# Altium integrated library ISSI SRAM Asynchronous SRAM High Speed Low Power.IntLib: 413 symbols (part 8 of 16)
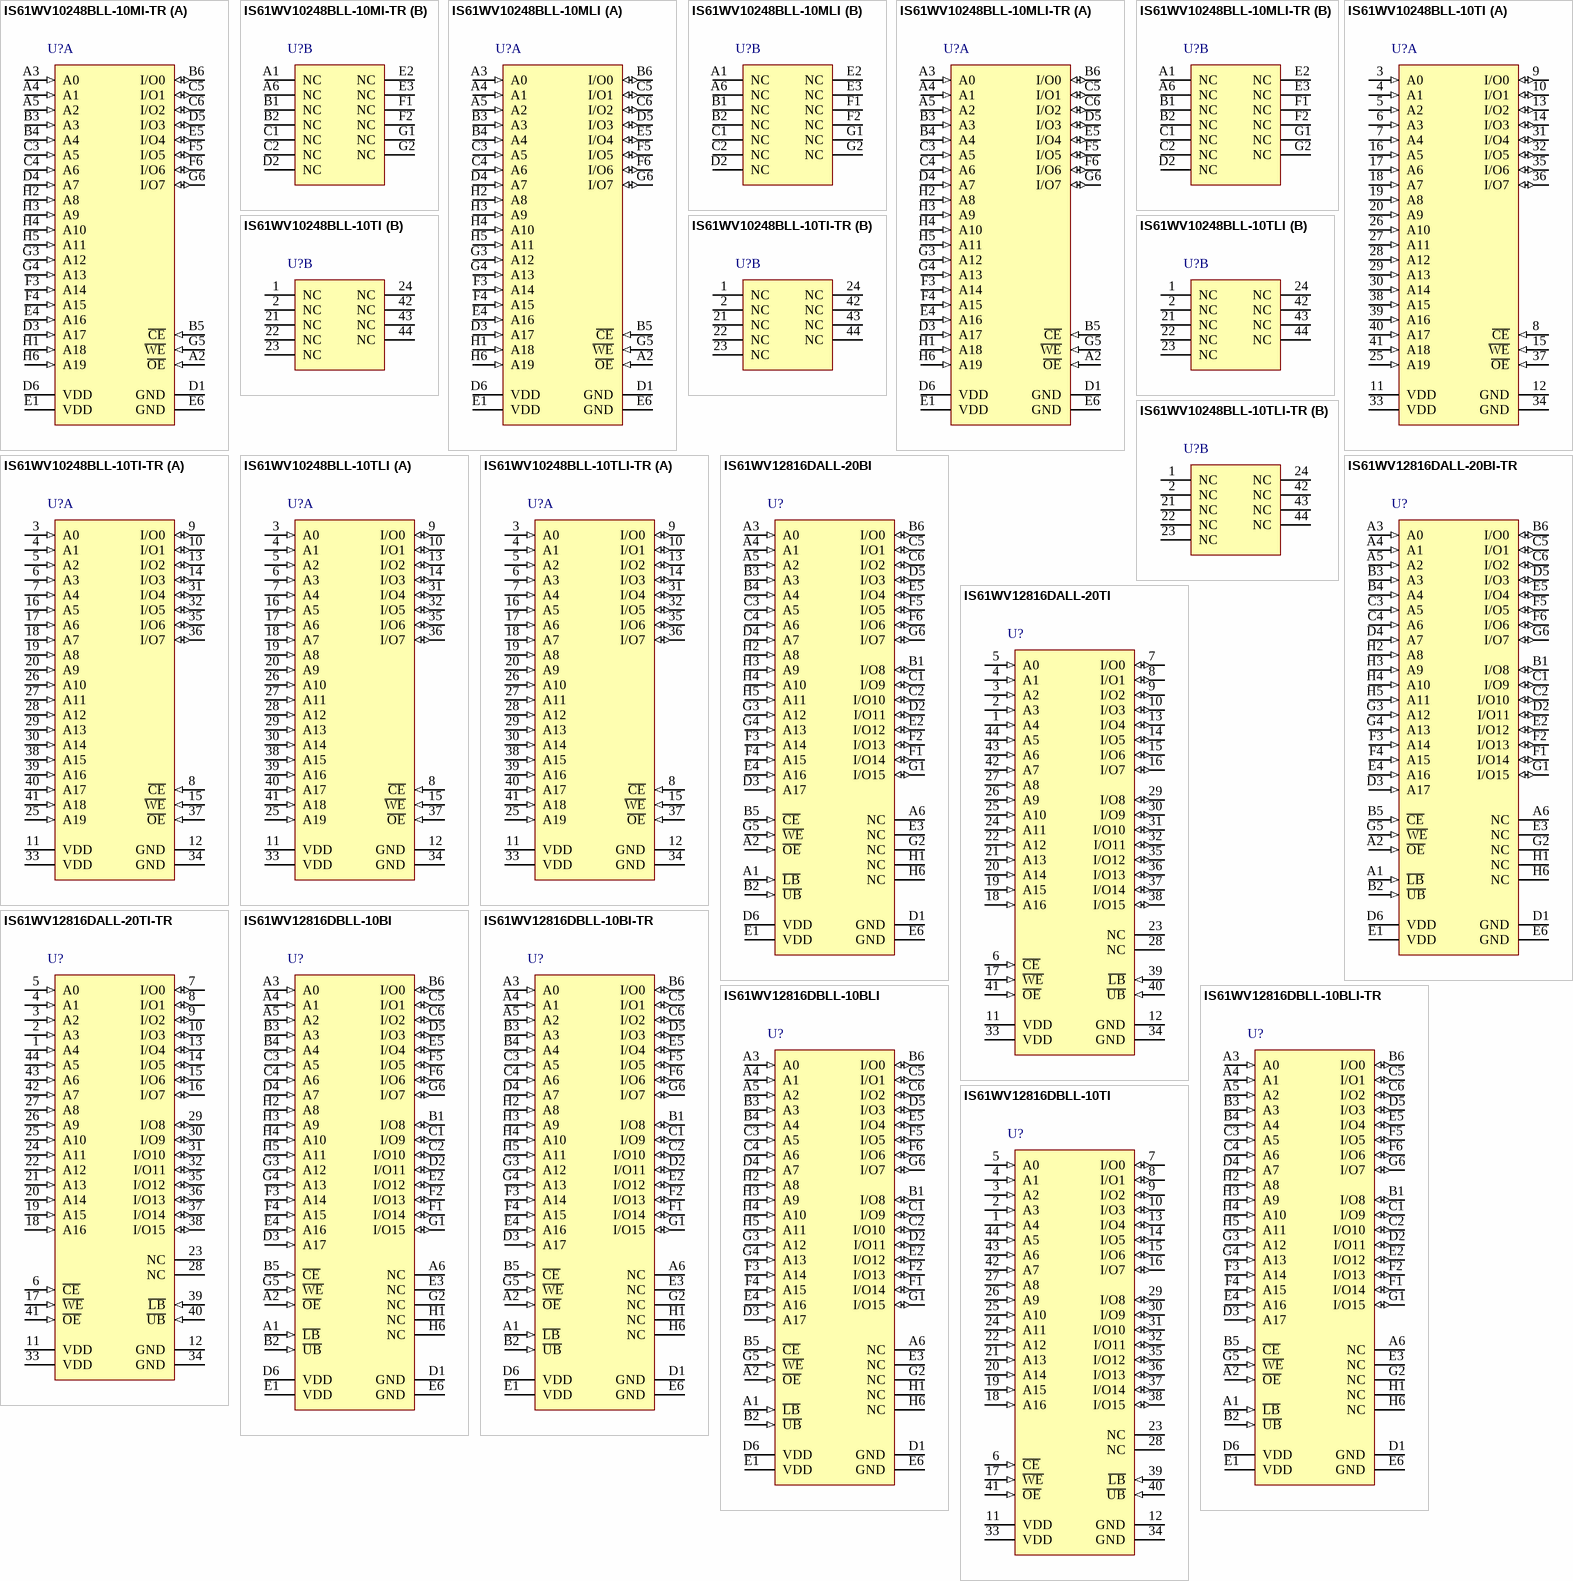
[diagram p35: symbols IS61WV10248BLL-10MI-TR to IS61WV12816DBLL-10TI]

## IS61WV12816DBLL-10BLI
designator U?
2 M High Speed Asynchronous CMOS SRAM, 128 K x 16, -40 to 85 degC, 48-Pin BGA (TF-BGA-48), Pb-Free; Manufacturer: Integrated Silicon Solution Inc (ISSI); PartNumber: IS61WV12816DBLL-10BLI; Packing: Tray / Tube; Speed (ns): 10
footprint ISSI-TF-BGA-48-6000X8000DE (BGA, 48-Balls, Body 8x6mm, Pitch 0.75mm)
pins: A1 ~{LB} (in) "Lower-byte Control (I/O0-I/O7)", A2 ~{OE} (in) "Output Enable Input", A3 A0 (in) "Address Input", A4 A1 (in) "Address Input", A5 A2 (in) "Address Input", A6 NC "No Connection", B1 I/O8 (io) "Data Input/Output", B2 ~{UB} (in) "Upper-byte Control (I/O8-I/O15)", B3 A3 (in) "Address Input", B4 A4 (in) "Address Input", B5 ~{CE} (in) "Chip Enable Input", B6 I/O0 (io) "Data Input/Output", C1 I/O9 (io) "Data Input/Output", C2 I/O10 (io) "Data Input/Output", C3 A5 (in) "Address Input", C4 A6 (in) "Address Input", C5 I/O1 (io) "Data Input/Output", C6 I/O2 (io) "Data Input/Output", D1 GND (power) "Ground", D2 I/O11 (io) "Data Input/Output", D3 A17 (in) "Address Input", D4 A7 (in) "Address Input", D5 I/O3 (io) "Data Input/Output", D6 VDD (power) "Power", E1 VDD (power) "Power", E2 I/O12 (io) "Data Input/Output", E3 NC "No Connection", E4 A16 (in) "Address Input", E5 I/O4 (io) "Data Input/Output", E6 GND (power) "Ground", F1 I/O14 (io) "Data Input/Output", F2 I/O13 (io) "Data Input/Output", F3 A14 (in) "Address Input", F4 A15 (in) "Address Input", F5 I/O5 (io) "Data Input/Output", F6 I/O6 (io) "Data Input/Output", G1 I/O15 (io) "Data Input/Output", G2 NC "No Connection", G3 A12 (in) "Address Input", G4 A13 (in) "Address Input", G5 ~{WE} (in) "Write Enable Input", G6 I/O7 (io) "Data Input/Output", H1 NC "No Connection", H2 A8 (in) "Address Input", H3 A9 (in) "Address Input", H4 A10 (in) "Address Input", H5 A11 (in) "Address Input", H6 NC "No Connection"

## IS61WV12816DBLL-10BLI-TR
designator U?
2 M High Speed Asynchronous CMOS SRAM, 128 K x 16, -40 to 85 degC, 48-Pin BGA (TF-BGA-48), Pb-Free; Manufacturer: Integrated Silicon Solution Inc (ISSI); PartNumber: IS61WV12816DBLL-10BLI-TR; Packing: Tape & Reel; Speed (ns): 10
footprint ISSI-TF-BGA-48-6000X8000DE (BGA, 48-Balls, Body 8x6mm, Pitch 0.75mm)
pins: A1 ~{LB} (in) "Lower-byte Control (I/O0-I/O7)", A2 ~{OE} (in) "Output Enable Input", A3 A0 (in) "Address Input", A4 A1 (in) "Address Input", A5 A2 (in) "Address Input", A6 NC "No Connection", B1 I/O8 (io) "Data Input/Output", B2 ~{UB} (in) "Upper-byte Control (I/O8-I/O15)", B3 A3 (in) "Address Input", B4 A4 (in) "Address Input", B5 ~{CE} (in) "Chip Enable Input", B6 I/O0 (io) "Data Input/Output", C1 I/O9 (io) "Data Input/Output", C2 I/O10 (io) "Data Input/Output", C3 A5 (in) "Address Input", C4 A6 (in) "Address Input", C5 I/O1 (io) "Data Input/Output", C6 I/O2 (io) "Data Input/Output", D1 GND (power) "Ground", D2 I/O11 (io) "Data Input/Output", D3 A17 (in) "Address Input", D4 A7 (in) "Address Input", D5 I/O3 (io) "Data Input/Output", D6 VDD (power) "Power", E1 VDD (power) "Power", E2 I/O12 (io) "Data Input/Output", E3 NC "No Connection", E4 A16 (in) "Address Input", E5 I/O4 (io) "Data Input/Output", E6 GND (power) "Ground", F1 I/O14 (io) "Data Input/Output", F2 I/O13 (io) "Data Input/Output", F3 A14 (in) "Address Input", F4 A15 (in) "Address Input", F5 I/O5 (io) "Data Input/Output", F6 I/O6 (io) "Data Input/Output", G1 I/O15 (io) "Data Input/Output", G2 NC "No Connection", G3 A12 (in) "Address Input", G4 A13 (in) "Address Input", G5 ~{WE} (in) "Write Enable Input", G6 I/O7 (io) "Data Input/Output", H1 NC "No Connection", H2 A8 (in) "Address Input", H3 A9 (in) "Address Input", H4 A10 (in) "Address Input", H5 A11 (in) "Address Input", H6 NC "No Connection"

## IS61WV12816DBLL-10TI
designator U?
2 M High Speed Asynchronous CMOS SRAM, 128 K x 16, -40 to 85 degC, 44-Pin SOP (TSOP-2-44); Manufacturer: Integrated Silicon Solution Inc (ISSI); PartNumber: IS61WV12816DBLL-10TI; Packing: Tray / Tube; Speed (ns): 10
footprint ISSI-TSOP-2-44_N (SOP, 44-Leads, Body 18.5x10.3mm, Pitch 0.8mm, IPC Medium Density)
pins: 1 A4 (in) "Address Input", 2 A3 (in) "Address Input", 3 A2 (in) "Address Input", 4 A1 (in) "Address Input", 5 A0 (in) "Address Input", 6 ~{CE} (in) "Chip Enable Input", 7 I/O0 (io) "Data Input/Output", 8 I/O1 (io) "Data Input/Output", 9 I/O2 (io) "Data Input/Output", 10 I/O3 (io) "Data Input/Output", 11 VDD (power) "Power", 12 GND (power) "Ground", 13 I/O4 (io) "Data Input/Output", 14 I/O5 (io) "Data Input/Output", 15 I/O6 (io) "Data Input/Output", 16 I/O7 (io) "Data Input/Output", 17 ~{WE} (in) "Write Enable Input", 18 A16 (in) "Address Input", 19 A15 (in) "Address Input", 20 A14 (in) "Address Input", 21 A13 (in) "Address Input", 22 A12 (in) "Address Input", 23 NC "No Connection", 24 A11 (in) "Address Input", 25 A10 (in) "Address Input", 26 A9 (in) "Address Input", 27 A8 (in) "Address Input", 28 NC "No Connection", 29 I/O8 (io) "Data Input/Output", 30 I/O9 (io) "Data Input/Output", 31 I/O10 (io) "Data Input/Output", 32 I/O11 (io) "Data Input/Output", 33 VDD (power) "Power", 34 GND (power) "Ground", 35 I/O12 (io) "Data Input/Output", 36 I/O13 (io) "Data Input/Output", 37 I/O14 (io) "Data Input/Output", 38 I/O15 (io) "Data Input/Output", 39 ~{LB} (in) "Lower-byte Control (I/O0-I/O7)", 40 ~{UB} (in) "Upper-byte Control (I/O8-I/O15)", 41 ~{OE} (in) "Output Enable Input", 42 A7 (in) "Address Input", 43 A6 (in) "Address Input", 44 A5 (in) "Address Input"

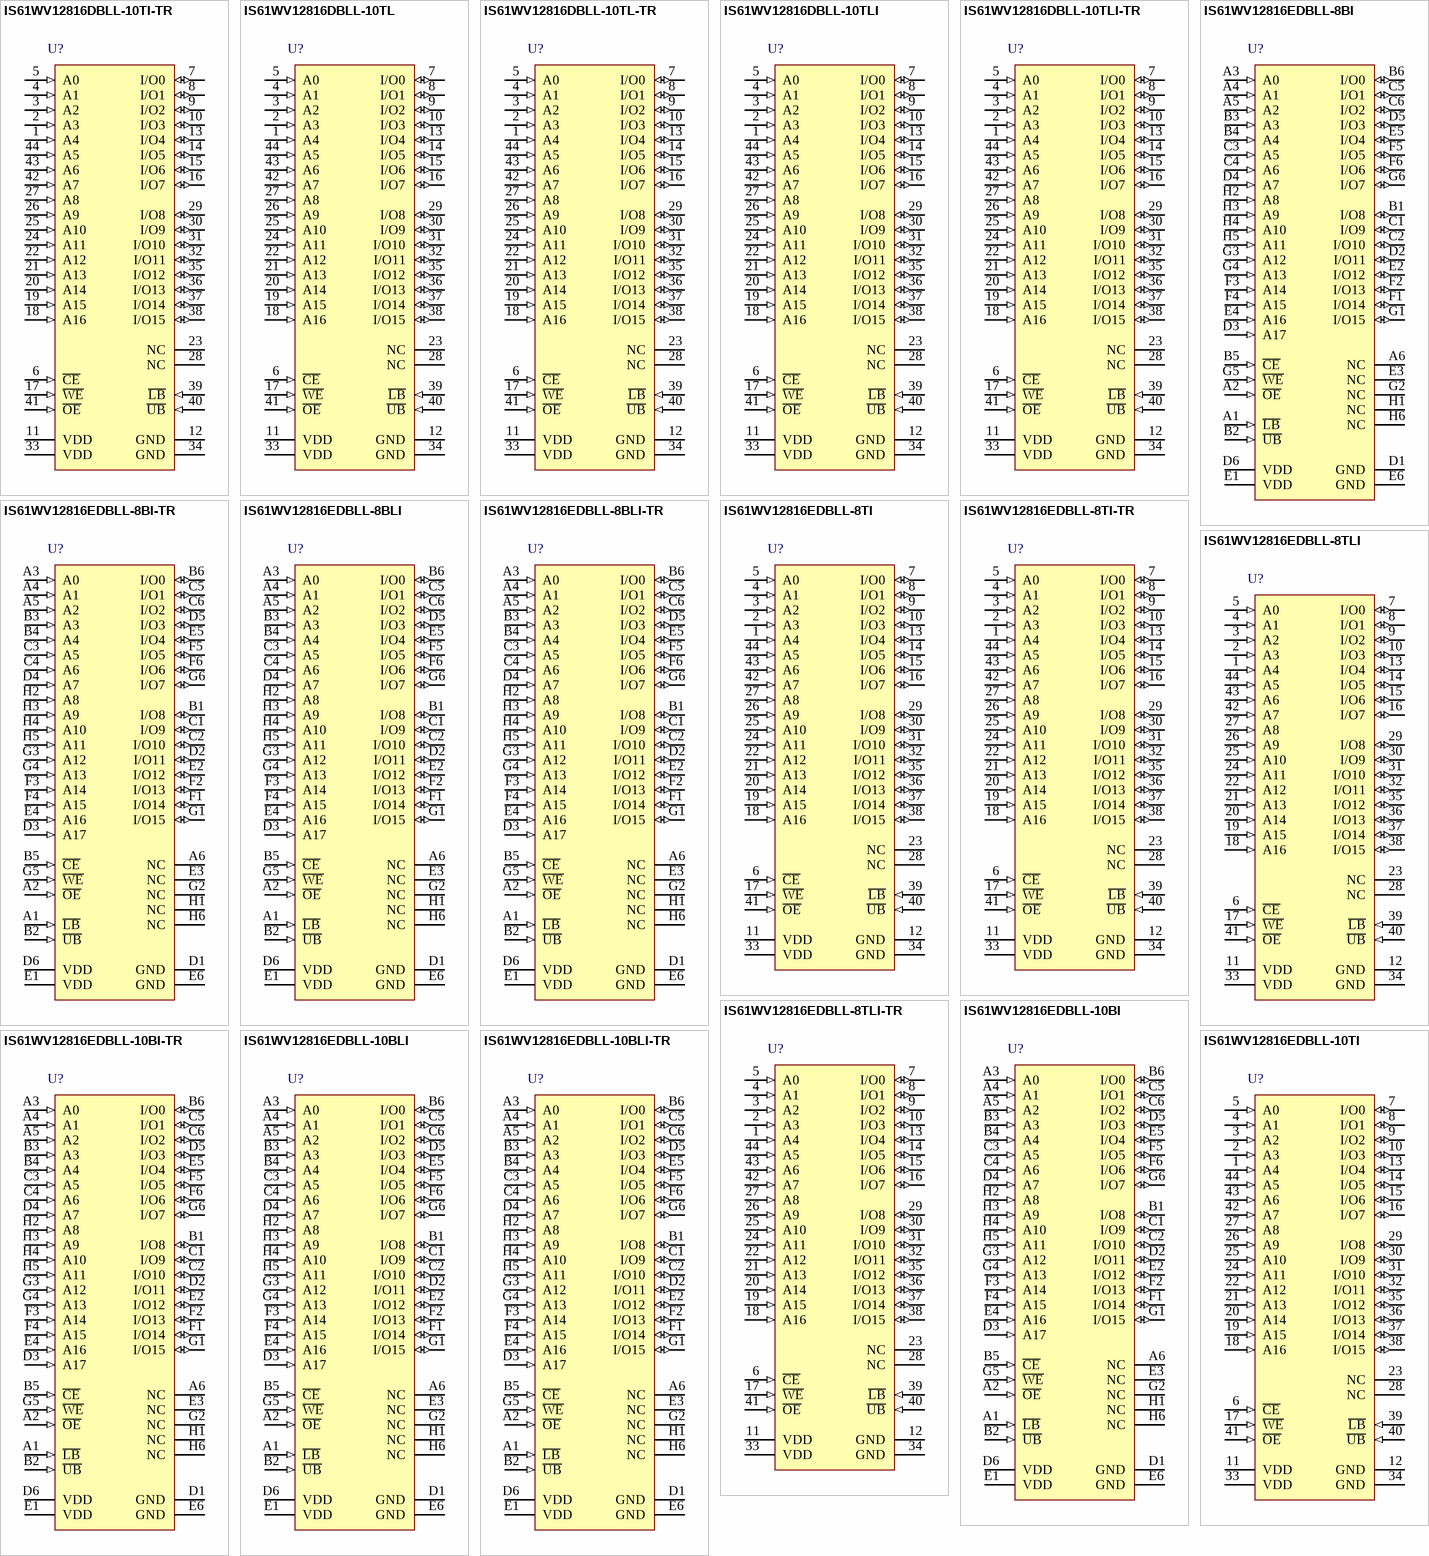
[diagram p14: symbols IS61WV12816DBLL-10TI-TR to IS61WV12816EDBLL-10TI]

## IS61WV12816DBLL-10TI-TR
designator U?
2 M High Speed Asynchronous CMOS SRAM, 128 K x 16, -40 to 85 degC, 44-Pin SOP (TSOP-2-44); Manufacturer: Integrated Silicon Solution Inc (ISSI); PartNumber: IS61WV12816DBLL-10TI-TR; Packing: Tape & Reel; Speed (ns): 10
footprint ISSI-TSOP-2-44_N (SOP, 44-Leads, Body 18.5x10.3mm, Pitch 0.8mm, IPC Medium Density)
pins: 1 A4 (in) "Address Input", 2 A3 (in) "Address Input", 3 A2 (in) "Address Input", 4 A1 (in) "Address Input", 5 A0 (in) "Address Input", 6 ~{CE} (in) "Chip Enable Input", 7 I/O0 (io) "Data Input/Output", 8 I/O1 (io) "Data Input/Output", 9 I/O2 (io) "Data Input/Output", 10 I/O3 (io) "Data Input/Output", 11 VDD (power) "Power", 12 GND (power) "Ground", 13 I/O4 (io) "Data Input/Output", 14 I/O5 (io) "Data Input/Output", 15 I/O6 (io) "Data Input/Output", 16 I/O7 (io) "Data Input/Output", 17 ~{WE} (in) "Write Enable Input", 18 A16 (in) "Address Input", 19 A15 (in) "Address Input", 20 A14 (in) "Address Input", 21 A13 (in) "Address Input", 22 A12 (in) "Address Input", 23 NC "No Connection", 24 A11 (in) "Address Input", 25 A10 (in) "Address Input", 26 A9 (in) "Address Input", 27 A8 (in) "Address Input", 28 NC "No Connection", 29 I/O8 (io) "Data Input/Output", 30 I/O9 (io) "Data Input/Output", 31 I/O10 (io) "Data Input/Output", 32 I/O11 (io) "Data Input/Output", 33 VDD (power) "Power", 34 GND (power) "Ground", 35 I/O12 (io) "Data Input/Output", 36 I/O13 (io) "Data Input/Output", 37 I/O14 (io) "Data Input/Output", 38 I/O15 (io) "Data Input/Output", 39 ~{LB} (in) "Lower-byte Control (I/O0-I/O7)", 40 ~{UB} (in) "Upper-byte Control (I/O8-I/O15)", 41 ~{OE} (in) "Output Enable Input", 42 A7 (in) "Address Input", 43 A6 (in) "Address Input", 44 A5 (in) "Address Input"

## IS61WV12816DBLL-10TL
designator U?
2 M High Speed Asynchronous CMOS SRAM, 128 K x 16, 0 to 70 degC, 44-Pin SOP (TSOP-2-44), Pb-Free; Manufacturer: Integrated Silicon Solution Inc (ISSI); PartNumber: IS61WV12816DBLL-10TL; Packing: Tray / Tube; Speed (ns): 10
footprint ISSI-TSOP-2-44_N (SOP, 44-Leads, Body 18.5x10.3mm, Pitch 0.8mm, IPC Medium Density)
pins: 1 A4 (in) "Address Input", 2 A3 (in) "Address Input", 3 A2 (in) "Address Input", 4 A1 (in) "Address Input", 5 A0 (in) "Address Input", 6 ~{CE} (in) "Chip Enable Input", 7 I/O0 (io) "Data Input/Output", 8 I/O1 (io) "Data Input/Output", 9 I/O2 (io) "Data Input/Output", 10 I/O3 (io) "Data Input/Output", 11 VDD (power) "Power", 12 GND (power) "Ground", 13 I/O4 (io) "Data Input/Output", 14 I/O5 (io) "Data Input/Output", 15 I/O6 (io) "Data Input/Output", 16 I/O7 (io) "Data Input/Output", 17 ~{WE} (in) "Write Enable Input", 18 A16 (in) "Address Input", 19 A15 (in) "Address Input", 20 A14 (in) "Address Input", 21 A13 (in) "Address Input", 22 A12 (in) "Address Input", 23 NC "No Connection", 24 A11 (in) "Address Input", 25 A10 (in) "Address Input", 26 A9 (in) "Address Input", 27 A8 (in) "Address Input", 28 NC "No Connection", 29 I/O8 (io) "Data Input/Output", 30 I/O9 (io) "Data Input/Output", 31 I/O10 (io) "Data Input/Output", 32 I/O11 (io) "Data Input/Output", 33 VDD (power) "Power", 34 GND (power) "Ground", 35 I/O12 (io) "Data Input/Output", 36 I/O13 (io) "Data Input/Output", 37 I/O14 (io) "Data Input/Output", 38 I/O15 (io) "Data Input/Output", 39 ~{LB} (in) "Lower-byte Control (I/O0-I/O7)", 40 ~{UB} (in) "Upper-byte Control (I/O8-I/O15)", 41 ~{OE} (in) "Output Enable Input", 42 A7 (in) "Address Input", 43 A6 (in) "Address Input", 44 A5 (in) "Address Input"

## IS61WV12816DBLL-10TL-TR
designator U?
2 M High Speed Asynchronous CMOS SRAM, 128 K x 16, 0 to 70 degC, 44-Pin SOP (TSOP-2-44), Pb-Free; Manufacturer: Integrated Silicon Solution Inc (ISSI); PartNumber: IS61WV12816DBLL-10TL-TR; Packing: Tape & Reel; Speed (ns): 10
footprint ISSI-TSOP-2-44_N (SOP, 44-Leads, Body 18.5x10.3mm, Pitch 0.8mm, IPC Medium Density)
pins: 1 A4 (in) "Address Input", 2 A3 (in) "Address Input", 3 A2 (in) "Address Input", 4 A1 (in) "Address Input", 5 A0 (in) "Address Input", 6 ~{CE} (in) "Chip Enable Input", 7 I/O0 (io) "Data Input/Output", 8 I/O1 (io) "Data Input/Output", 9 I/O2 (io) "Data Input/Output", 10 I/O3 (io) "Data Input/Output", 11 VDD (power) "Power", 12 GND (power) "Ground", 13 I/O4 (io) "Data Input/Output", 14 I/O5 (io) "Data Input/Output", 15 I/O6 (io) "Data Input/Output", 16 I/O7 (io) "Data Input/Output", 17 ~{WE} (in) "Write Enable Input", 18 A16 (in) "Address Input", 19 A15 (in) "Address Input", 20 A14 (in) "Address Input", 21 A13 (in) "Address Input", 22 A12 (in) "Address Input", 23 NC "No Connection", 24 A11 (in) "Address Input", 25 A10 (in) "Address Input", 26 A9 (in) "Address Input", 27 A8 (in) "Address Input", 28 NC "No Connection", 29 I/O8 (io) "Data Input/Output", 30 I/O9 (io) "Data Input/Output", 31 I/O10 (io) "Data Input/Output", 32 I/O11 (io) "Data Input/Output", 33 VDD (power) "Power", 34 GND (power) "Ground", 35 I/O12 (io) "Data Input/Output", 36 I/O13 (io) "Data Input/Output", 37 I/O14 (io) "Data Input/Output", 38 I/O15 (io) "Data Input/Output", 39 ~{LB} (in) "Lower-byte Control (I/O0-I/O7)", 40 ~{UB} (in) "Upper-byte Control (I/O8-I/O15)", 41 ~{OE} (in) "Output Enable Input", 42 A7 (in) "Address Input", 43 A6 (in) "Address Input", 44 A5 (in) "Address Input"

## IS61WV12816DBLL-10TLI
designator U?
2 M High Speed Asynchronous CMOS SRAM, 128 K x 16, -40 to 85 degC, 44-Pin SOP (TSOP-2-44), Pb-Free; Manufacturer: Integrated Silicon Solution Inc (ISSI); PartNumber: IS61WV12816DBLL-10TLI; Packing: Tray / Tube; Speed (ns): 10
footprint ISSI-TSOP-2-44_N (SOP, 44-Leads, Body 18.5x10.3mm, Pitch 0.8mm, IPC Medium Density)
pins: 1 A4 (in) "Address Input", 2 A3 (in) "Address Input", 3 A2 (in) "Address Input", 4 A1 (in) "Address Input", 5 A0 (in) "Address Input", 6 ~{CE} (in) "Chip Enable Input", 7 I/O0 (io) "Data Input/Output", 8 I/O1 (io) "Data Input/Output", 9 I/O2 (io) "Data Input/Output", 10 I/O3 (io) "Data Input/Output", 11 VDD (power) "Power", 12 GND (power) "Ground", 13 I/O4 (io) "Data Input/Output", 14 I/O5 (io) "Data Input/Output", 15 I/O6 (io) "Data Input/Output", 16 I/O7 (io) "Data Input/Output", 17 ~{WE} (in) "Write Enable Input", 18 A16 (in) "Address Input", 19 A15 (in) "Address Input", 20 A14 (in) "Address Input", 21 A13 (in) "Address Input", 22 A12 (in) "Address Input", 23 NC "No Connection", 24 A11 (in) "Address Input", 25 A10 (in) "Address Input", 26 A9 (in) "Address Input", 27 A8 (in) "Address Input", 28 NC "No Connection", 29 I/O8 (io) "Data Input/Output", 30 I/O9 (io) "Data Input/Output", 31 I/O10 (io) "Data Input/Output", 32 I/O11 (io) "Data Input/Output", 33 VDD (power) "Power", 34 GND (power) "Ground", 35 I/O12 (io) "Data Input/Output", 36 I/O13 (io) "Data Input/Output", 37 I/O14 (io) "Data Input/Output", 38 I/O15 (io) "Data Input/Output", 39 ~{LB} (in) "Lower-byte Control (I/O0-I/O7)", 40 ~{UB} (in) "Upper-byte Control (I/O8-I/O15)", 41 ~{OE} (in) "Output Enable Input", 42 A7 (in) "Address Input", 43 A6 (in) "Address Input", 44 A5 (in) "Address Input"

## IS61WV12816DBLL-10TLI-TR
designator U?
2 M High Speed Asynchronous CMOS SRAM, 128 K x 16, -40 to 85 degC, 44-Pin SOP (TSOP-2-44), Pb-Free; Manufacturer: Integrated Silicon Solution Inc (ISSI); PartNumber: IS61WV12816DBLL-10TLI-TR; Packing: Tape & Reel; Speed (ns): 10
footprint ISSI-TSOP-2-44_N (SOP, 44-Leads, Body 18.5x10.3mm, Pitch 0.8mm, IPC Medium Density)
pins: 1 A4 (in) "Address Input", 2 A3 (in) "Address Input", 3 A2 (in) "Address Input", 4 A1 (in) "Address Input", 5 A0 (in) "Address Input", 6 ~{CE} (in) "Chip Enable Input", 7 I/O0 (io) "Data Input/Output", 8 I/O1 (io) "Data Input/Output", 9 I/O2 (io) "Data Input/Output", 10 I/O3 (io) "Data Input/Output", 11 VDD (power) "Power", 12 GND (power) "Ground", 13 I/O4 (io) "Data Input/Output", 14 I/O5 (io) "Data Input/Output", 15 I/O6 (io) "Data Input/Output", 16 I/O7 (io) "Data Input/Output", 17 ~{WE} (in) "Write Enable Input", 18 A16 (in) "Address Input", 19 A15 (in) "Address Input", 20 A14 (in) "Address Input", 21 A13 (in) "Address Input", 22 A12 (in) "Address Input", 23 NC "No Connection", 24 A11 (in) "Address Input", 25 A10 (in) "Address Input", 26 A9 (in) "Address Input", 27 A8 (in) "Address Input", 28 NC "No Connection", 29 I/O8 (io) "Data Input/Output", 30 I/O9 (io) "Data Input/Output", 31 I/O10 (io) "Data Input/Output", 32 I/O11 (io) "Data Input/Output", 33 VDD (power) "Power", 34 GND (power) "Ground", 35 I/O12 (io) "Data Input/Output", 36 I/O13 (io) "Data Input/Output", 37 I/O14 (io) "Data Input/Output", 38 I/O15 (io) "Data Input/Output", 39 ~{LB} (in) "Lower-byte Control (I/O0-I/O7)", 40 ~{UB} (in) "Upper-byte Control (I/O8-I/O15)", 41 ~{OE} (in) "Output Enable Input", 42 A7 (in) "Address Input", 43 A6 (in) "Address Input", 44 A5 (in) "Address Input"

## IS61WV12816EDBLL-8BI
designator U?
2 M High Speed Asynchronous CMOS SRAM with ECC, 128 K x 16, -40 to 85 degC, 48-Pin BGA (TF-BGA-48); Manufacturer: Integrated Silicon Solution Inc (ISSI); PartNumber: IS61WV12816EDBLL-8BI; Density: 2M; Packing: Tray / Tube; Speed (ns): 8
footprint ISSI-TF-BGA-48-6000X8000DE (BGA, 48-Balls, Body 8x6mm, Pitch 0.75mm)
pins: A1 ~{LB} (in) "Lower-byte Control (I/O0-I/O7)", A2 ~{OE} (in) "Output Enable Input", A3 A0 (in) "Address Input", A4 A1 (in) "Address Input", A5 A2 (in) "Address Input", A6 NC "No Connection", B1 I/O8 (io) "Data Input/Output", B2 ~{UB} (in) "Upper-byte Control (I/O8-I/O15)", B3 A3 (in) "Address Input", B4 A4 (in) "Address Input", B5 ~{CE} (in) "Chip Enable Input", B6 I/O0 (io) "Data Input/Output", C1 I/O9 (io) "Data Input/Output", C2 I/O10 (io) "Data Input/Output", C3 A5 (in) "Address Input", C4 A6 (in) "Address Input", C5 I/O1 (io) "Data Input/Output", C6 I/O2 (io) "Data Input/Output", D1 GND (power) "Ground", D2 I/O11 (io) "Data Input/Output", D3 A17 (in) "Address Input", D4 A7 (in) "Address Input", D5 I/O3 (io) "Data Input/Output", D6 VDD (power) "Power", E1 VDD (power) "Power", E2 I/O12 (io) "Data Input/Output", E3 NC "No Connection", E4 A16 (in) "Address Input", E5 I/O4 (io) "Data Input/Output", E6 GND (power) "Ground", F1 I/O14 (io) "Data Input/Output", F2 I/O13 (io) "Data Input/Output", F3 A14 (in) "Address Input", F4 A15 (in) "Address Input", F5 I/O5 (io) "Data Input/Output", F6 I/O6 (io) "Data Input/Output", G1 I/O15 (io) "Data Input/Output", G2 NC "No Connection", G3 A12 (in) "Address Input", G4 A13 (in) "Address Input", G5 ~{WE} (in) "Write Enable Input", G6 I/O7 (io) "Data Input/Output", H1 NC "No Connection", H2 A8 (in) "Address Input", H3 A9 (in) "Address Input", H4 A10 (in) "Address Input", H5 A11 (in) "Address Input", H6 NC "No Connection"

## IS61WV12816EDBLL-8BI-TR
designator U?
2 M High Speed Asynchronous CMOS SRAM with ECC, 128 K x 16, -40 to 85 degC, 48-Pin BGA (TF-BGA-48); Manufacturer: Integrated Silicon Solution Inc (ISSI); PartNumber: IS61WV12816EDBLL-8BI-TR; Density: 2M; Packing: Tape & Reel; Speed (ns): 8
footprint ISSI-TF-BGA-48-6000X8000DE (BGA, 48-Balls, Body 8x6mm, Pitch 0.75mm)
pins: A1 ~{LB} (in) "Lower-byte Control (I/O0-I/O7)", A2 ~{OE} (in) "Output Enable Input", A3 A0 (in) "Address Input", A4 A1 (in) "Address Input", A5 A2 (in) "Address Input", A6 NC "No Connection", B1 I/O8 (io) "Data Input/Output", B2 ~{UB} (in) "Upper-byte Control (I/O8-I/O15)", B3 A3 (in) "Address Input", B4 A4 (in) "Address Input", B5 ~{CE} (in) "Chip Enable Input", B6 I/O0 (io) "Data Input/Output", C1 I/O9 (io) "Data Input/Output", C2 I/O10 (io) "Data Input/Output", C3 A5 (in) "Address Input", C4 A6 (in) "Address Input", C5 I/O1 (io) "Data Input/Output", C6 I/O2 (io) "Data Input/Output", D1 GND (power) "Ground", D2 I/O11 (io) "Data Input/Output", D3 A17 (in) "Address Input", D4 A7 (in) "Address Input", D5 I/O3 (io) "Data Input/Output", D6 VDD (power) "Power", E1 VDD (power) "Power", E2 I/O12 (io) "Data Input/Output", E3 NC "No Connection", E4 A16 (in) "Address Input", E5 I/O4 (io) "Data Input/Output", E6 GND (power) "Ground", F1 I/O14 (io) "Data Input/Output", F2 I/O13 (io) "Data Input/Output", F3 A14 (in) "Address Input", F4 A15 (in) "Address Input", F5 I/O5 (io) "Data Input/Output", F6 I/O6 (io) "Data Input/Output", G1 I/O15 (io) "Data Input/Output", G2 NC "No Connection", G3 A12 (in) "Address Input", G4 A13 (in) "Address Input", G5 ~{WE} (in) "Write Enable Input", G6 I/O7 (io) "Data Input/Output", H1 NC "No Connection", H2 A8 (in) "Address Input", H3 A9 (in) "Address Input", H4 A10 (in) "Address Input", H5 A11 (in) "Address Input", H6 NC "No Connection"

## IS61WV12816EDBLL-8BLI
designator U?
2 M High Speed Asynchronous CMOS SRAM with ECC, 128 K x 16, -40 to 85 degC, 48-Pin BGA (TF-BGA-48), Pb-Free; Manufacturer: Integrated Silicon Solution Inc (ISSI); PartNumber: IS61WV12816EDBLL-8BLI; Density: 2M; Packing: Tray / Tube; Speed (ns): 8
footprint ISSI-TF-BGA-48-6000X8000DE (BGA, 48-Balls, Body 8x6mm, Pitch 0.75mm)
pins: A1 ~{LB} (in) "Lower-byte Control (I/O0-I/O7)", A2 ~{OE} (in) "Output Enable Input", A3 A0 (in) "Address Input", A4 A1 (in) "Address Input", A5 A2 (in) "Address Input", A6 NC "No Connection", B1 I/O8 (io) "Data Input/Output", B2 ~{UB} (in) "Upper-byte Control (I/O8-I/O15)", B3 A3 (in) "Address Input", B4 A4 (in) "Address Input", B5 ~{CE} (in) "Chip Enable Input", B6 I/O0 (io) "Data Input/Output", C1 I/O9 (io) "Data Input/Output", C2 I/O10 (io) "Data Input/Output", C3 A5 (in) "Address Input", C4 A6 (in) "Address Input", C5 I/O1 (io) "Data Input/Output", C6 I/O2 (io) "Data Input/Output", D1 GND (power) "Ground", D2 I/O11 (io) "Data Input/Output", D3 A17 (in) "Address Input", D4 A7 (in) "Address Input", D5 I/O3 (io) "Data Input/Output", D6 VDD (power) "Power", E1 VDD (power) "Power", E2 I/O12 (io) "Data Input/Output", E3 NC "No Connection", E4 A16 (in) "Address Input", E5 I/O4 (io) "Data Input/Output", E6 GND (power) "Ground", F1 I/O14 (io) "Data Input/Output", F2 I/O13 (io) "Data Input/Output", F3 A14 (in) "Address Input", F4 A15 (in) "Address Input", F5 I/O5 (io) "Data Input/Output", F6 I/O6 (io) "Data Input/Output", G1 I/O15 (io) "Data Input/Output", G2 NC "No Connection", G3 A12 (in) "Address Input", G4 A13 (in) "Address Input", G5 ~{WE} (in) "Write Enable Input", G6 I/O7 (io) "Data Input/Output", H1 NC "No Connection", H2 A8 (in) "Address Input", H3 A9 (in) "Address Input", H4 A10 (in) "Address Input", H5 A11 (in) "Address Input", H6 NC "No Connection"

## IS61WV12816EDBLL-8BLI-TR
designator U?
2 M High Speed Asynchronous CMOS SRAM with ECC, 128 K x 16, -40 to 85 degC, 48-Pin BGA (TF-BGA-48), Pb-Free; Manufacturer: Integrated Silicon Solution Inc (ISSI); PartNumber: IS61WV12816EDBLL-8BLI-TR; Density: 2M; Packing: Tape & Reel; Speed (ns): 8
footprint ISSI-TF-BGA-48-6000X8000DE (BGA, 48-Balls, Body 8x6mm, Pitch 0.75mm)
pins: A1 ~{LB} (in) "Lower-byte Control (I/O0-I/O7)", A2 ~{OE} (in) "Output Enable Input", A3 A0 (in) "Address Input", A4 A1 (in) "Address Input", A5 A2 (in) "Address Input", A6 NC "No Connection", B1 I/O8 (io) "Data Input/Output", B2 ~{UB} (in) "Upper-byte Control (I/O8-I/O15)", B3 A3 (in) "Address Input", B4 A4 (in) "Address Input", B5 ~{CE} (in) "Chip Enable Input", B6 I/O0 (io) "Data Input/Output", C1 I/O9 (io) "Data Input/Output", C2 I/O10 (io) "Data Input/Output", C3 A5 (in) "Address Input", C4 A6 (in) "Address Input", C5 I/O1 (io) "Data Input/Output", C6 I/O2 (io) "Data Input/Output", D1 GND (power) "Ground", D2 I/O11 (io) "Data Input/Output", D3 A17 (in) "Address Input", D4 A7 (in) "Address Input", D5 I/O3 (io) "Data Input/Output", D6 VDD (power) "Power", E1 VDD (power) "Power", E2 I/O12 (io) "Data Input/Output", E3 NC "No Connection", E4 A16 (in) "Address Input", E5 I/O4 (io) "Data Input/Output", E6 GND (power) "Ground", F1 I/O14 (io) "Data Input/Output", F2 I/O13 (io) "Data Input/Output", F3 A14 (in) "Address Input", F4 A15 (in) "Address Input", F5 I/O5 (io) "Data Input/Output", F6 I/O6 (io) "Data Input/Output", G1 I/O15 (io) "Data Input/Output", G2 NC "No Connection", G3 A12 (in) "Address Input", G4 A13 (in) "Address Input", G5 ~{WE} (in) "Write Enable Input", G6 I/O7 (io) "Data Input/Output", H1 NC "No Connection", H2 A8 (in) "Address Input", H3 A9 (in) "Address Input", H4 A10 (in) "Address Input", H5 A11 (in) "Address Input", H6 NC "No Connection"

## IS61WV12816EDBLL-8TI
designator U?
2 M High Speed Asynchronous CMOS SRAM with ECC, 128 K x 16, -40 to 85 degC, 44-Pin SOP (TSOP-2-44); Manufacturer: Integrated Silicon Solution Inc (ISSI); PartNumber: IS61WV12816EDBLL-8TI; Density: 2M; Packing: Tray / Tube; Speed (ns): 8
footprint ISSI-TSOP-2-44_N (SOP, 44-Leads, Body 18.5x10.3mm, Pitch 0.8mm, IPC Medium Density)
pins: 1 A4 (in) "Address Input", 2 A3 (in) "Address Input", 3 A2 (in) "Address Input", 4 A1 (in) "Address Input", 5 A0 (in) "Address Input", 6 ~{CE} (in) "Chip Enable Input", 7 I/O0 (io) "Data Input/Output", 8 I/O1 (io) "Data Input/Output", 9 I/O2 (io) "Data Input/Output", 10 I/O3 (io) "Data Input/Output", 11 VDD (power) "Power", 12 GND (power) "Ground", 13 I/O4 (io) "Data Input/Output", 14 I/O5 (io) "Data Input/Output", 15 I/O6 (io) "Data Input/Output", 16 I/O7 (io) "Data Input/Output", 17 ~{WE} (in) "Write Enable Input", 18 A16 (in) "Address Input", 19 A15 (in) "Address Input", 20 A14 (in) "Address Input", 21 A13 (in) "Address Input", 22 A12 (in) "Address Input", 23 NC "No Connection", 24 A11 (in) "Address Input", 25 A10 (in) "Address Input", 26 A9 (in) "Address Input", 27 A8 (in) "Address Input", 28 NC "No Connection", 29 I/O8 (io) "Data Input/Output", 30 I/O9 (io) "Data Input/Output", 31 I/O10 (io) "Data Input/Output", 32 I/O11 (io) "Data Input/Output", 33 VDD (power) "Power", 34 GND (power) "Ground", 35 I/O12 (io) "Data Input/Output", 36 I/O13 (io) "Data Input/Output", 37 I/O14 (io) "Data Input/Output", 38 I/O15 (io) "Data Input/Output", 39 ~{LB} (in) "Lower-byte Control (I/O0-I/O7)", 40 ~{UB} (in) "Upper-byte Control (I/O8-I/O15)", 41 ~{OE} (in) "Output Enable Input", 42 A7 (in) "Address Input", 43 A6 (in) "Address Input", 44 A5 (in) "Address Input"

## IS61WV12816EDBLL-8TI-TR
designator U?
2 M High Speed Asynchronous CMOS SRAM with ECC, 128 K x 16, -40 to 85 degC, 44-Pin SOP (TSOP-2-44); Manufacturer: Integrated Silicon Solution Inc (ISSI); PartNumber: IS61WV12816EDBLL-8TI-TR; Density: 2M; Packing: Tape & Reel; Speed (ns): 8
footprint ISSI-TSOP-2-44_N (SOP, 44-Leads, Body 18.5x10.3mm, Pitch 0.8mm, IPC Medium Density)
pins: 1 A4 (in) "Address Input", 2 A3 (in) "Address Input", 3 A2 (in) "Address Input", 4 A1 (in) "Address Input", 5 A0 (in) "Address Input", 6 ~{CE} (in) "Chip Enable Input", 7 I/O0 (io) "Data Input/Output", 8 I/O1 (io) "Data Input/Output", 9 I/O2 (io) "Data Input/Output", 10 I/O3 (io) "Data Input/Output", 11 VDD (power) "Power", 12 GND (power) "Ground", 13 I/O4 (io) "Data Input/Output", 14 I/O5 (io) "Data Input/Output", 15 I/O6 (io) "Data Input/Output", 16 I/O7 (io) "Data Input/Output", 17 ~{WE} (in) "Write Enable Input", 18 A16 (in) "Address Input", 19 A15 (in) "Address Input", 20 A14 (in) "Address Input", 21 A13 (in) "Address Input", 22 A12 (in) "Address Input", 23 NC "No Connection", 24 A11 (in) "Address Input", 25 A10 (in) "Address Input", 26 A9 (in) "Address Input", 27 A8 (in) "Address Input", 28 NC "No Connection", 29 I/O8 (io) "Data Input/Output", 30 I/O9 (io) "Data Input/Output", 31 I/O10 (io) "Data Input/Output", 32 I/O11 (io) "Data Input/Output", 33 VDD (power) "Power", 34 GND (power) "Ground", 35 I/O12 (io) "Data Input/Output", 36 I/O13 (io) "Data Input/Output", 37 I/O14 (io) "Data Input/Output", 38 I/O15 (io) "Data Input/Output", 39 ~{LB} (in) "Lower-byte Control (I/O0-I/O7)", 40 ~{UB} (in) "Upper-byte Control (I/O8-I/O15)", 41 ~{OE} (in) "Output Enable Input", 42 A7 (in) "Address Input", 43 A6 (in) "Address Input", 44 A5 (in) "Address Input"

## IS61WV12816EDBLL-8TLI
designator U?
2 M High Speed Asynchronous CMOS SRAM with ECC, 128 K x 16, -40 to 85 degC, 44-Pin SOP (TSOP-2-44), Pb-Free; Manufacturer: Integrated Silicon Solution Inc (ISSI); PartNumber: IS61WV12816EDBLL-8TLI; Density: 2M; Packing: Tray / Tube; Speed (ns): 8
footprint ISSI-TSOP-2-44_N (SOP, 44-Leads, Body 18.5x10.3mm, Pitch 0.8mm, IPC Medium Density)
pins: 1 A4 (in) "Address Input", 2 A3 (in) "Address Input", 3 A2 (in) "Address Input", 4 A1 (in) "Address Input", 5 A0 (in) "Address Input", 6 ~{CE} (in) "Chip Enable Input", 7 I/O0 (io) "Data Input/Output", 8 I/O1 (io) "Data Input/Output", 9 I/O2 (io) "Data Input/Output", 10 I/O3 (io) "Data Input/Output", 11 VDD (power) "Power", 12 GND (power) "Ground", 13 I/O4 (io) "Data Input/Output", 14 I/O5 (io) "Data Input/Output", 15 I/O6 (io) "Data Input/Output", 16 I/O7 (io) "Data Input/Output", 17 ~{WE} (in) "Write Enable Input", 18 A16 (in) "Address Input", 19 A15 (in) "Address Input", 20 A14 (in) "Address Input", 21 A13 (in) "Address Input", 22 A12 (in) "Address Input", 23 NC "No Connection", 24 A11 (in) "Address Input", 25 A10 (in) "Address Input", 26 A9 (in) "Address Input", 27 A8 (in) "Address Input", 28 NC "No Connection", 29 I/O8 (io) "Data Input/Output", 30 I/O9 (io) "Data Input/Output", 31 I/O10 (io) "Data Input/Output", 32 I/O11 (io) "Data Input/Output", 33 VDD (power) "Power", 34 GND (power) "Ground", 35 I/O12 (io) "Data Input/Output", 36 I/O13 (io) "Data Input/Output", 37 I/O14 (io) "Data Input/Output", 38 I/O15 (io) "Data Input/Output", 39 ~{LB} (in) "Lower-byte Control (I/O0-I/O7)", 40 ~{UB} (in) "Upper-byte Control (I/O8-I/O15)", 41 ~{OE} (in) "Output Enable Input", 42 A7 (in) "Address Input", 43 A6 (in) "Address Input", 44 A5 (in) "Address Input"

## IS61WV12816EDBLL-8TLI-TR
designator U?
2 M High Speed Asynchronous CMOS SRAM with ECC, 128 K x 16, -40 to 85 degC, 44-Pin SOP (TSOP-2-44), Pb-Free; Manufacturer: Integrated Silicon Solution Inc (ISSI); PartNumber: IS61WV12816EDBLL-8TLI-TR; Density: 2M; Packing: Tape & Reel; Speed (ns): 8
footprint ISSI-TSOP-2-44_N (SOP, 44-Leads, Body 18.5x10.3mm, Pitch 0.8mm, IPC Medium Density)
pins: 1 A4 (in) "Address Input", 2 A3 (in) "Address Input", 3 A2 (in) "Address Input", 4 A1 (in) "Address Input", 5 A0 (in) "Address Input", 6 ~{CE} (in) "Chip Enable Input", 7 I/O0 (io) "Data Input/Output", 8 I/O1 (io) "Data Input/Output", 9 I/O2 (io) "Data Input/Output", 10 I/O3 (io) "Data Input/Output", 11 VDD (power) "Power", 12 GND (power) "Ground", 13 I/O4 (io) "Data Input/Output", 14 I/O5 (io) "Data Input/Output", 15 I/O6 (io) "Data Input/Output", 16 I/O7 (io) "Data Input/Output", 17 ~{WE} (in) "Write Enable Input", 18 A16 (in) "Address Input", 19 A15 (in) "Address Input", 20 A14 (in) "Address Input", 21 A13 (in) "Address Input", 22 A12 (in) "Address Input", 23 NC "No Connection", 24 A11 (in) "Address Input", 25 A10 (in) "Address Input", 26 A9 (in) "Address Input", 27 A8 (in) "Address Input", 28 NC "No Connection", 29 I/O8 (io) "Data Input/Output", 30 I/O9 (io) "Data Input/Output", 31 I/O10 (io) "Data Input/Output", 32 I/O11 (io) "Data Input/Output", 33 VDD (power) "Power", 34 GND (power) "Ground", 35 I/O12 (io) "Data Input/Output", 36 I/O13 (io) "Data Input/Output", 37 I/O14 (io) "Data Input/Output", 38 I/O15 (io) "Data Input/Output", 39 ~{LB} (in) "Lower-byte Control (I/O0-I/O7)", 40 ~{UB} (in) "Upper-byte Control (I/O8-I/O15)", 41 ~{OE} (in) "Output Enable Input", 42 A7 (in) "Address Input", 43 A6 (in) "Address Input", 44 A5 (in) "Address Input"

## IS61WV12816EDBLL-10BI
designator U?
2 M High Speed Asynchronous CMOS SRAM with ECC, 128 K x 16, -40 to 85 degC, 48-Pin BGA (TF-BGA-48); Manufacturer: Integrated Silicon Solution Inc (ISSI); PartNumber: IS61WV12816EDBLL-10BI; Density: 2M; Packing: Tray / Tube; Speed (ns): 10
footprint ISSI-TF-BGA-48-6000X8000DE (BGA, 48-Balls, Body 8x6mm, Pitch 0.75mm)
pins: A1 ~{LB} (in) "Lower-byte Control (I/O0-I/O7)", A2 ~{OE} (in) "Output Enable Input", A3 A0 (in) "Address Input", A4 A1 (in) "Address Input", A5 A2 (in) "Address Input", A6 NC "No Connection", B1 I/O8 (io) "Data Input/Output", B2 ~{UB} (in) "Upper-byte Control (I/O8-I/O15)", B3 A3 (in) "Address Input", B4 A4 (in) "Address Input", B5 ~{CE} (in) "Chip Enable Input", B6 I/O0 (io) "Data Input/Output", C1 I/O9 (io) "Data Input/Output", C2 I/O10 (io) "Data Input/Output", C3 A5 (in) "Address Input", C4 A6 (in) "Address Input", C5 I/O1 (io) "Data Input/Output", C6 I/O2 (io) "Data Input/Output", D1 GND (power) "Ground", D2 I/O11 (io) "Data Input/Output", D3 A17 (in) "Address Input", D4 A7 (in) "Address Input", D5 I/O3 (io) "Data Input/Output", D6 VDD (power) "Power", E1 VDD (power) "Power", E2 I/O12 (io) "Data Input/Output", E3 NC "No Connection", E4 A16 (in) "Address Input", E5 I/O4 (io) "Data Input/Output", E6 GND (power) "Ground", F1 I/O14 (io) "Data Input/Output", F2 I/O13 (io) "Data Input/Output", F3 A14 (in) "Address Input", F4 A15 (in) "Address Input", F5 I/O5 (io) "Data Input/Output", F6 I/O6 (io) "Data Input/Output", G1 I/O15 (io) "Data Input/Output", G2 NC "No Connection", G3 A12 (in) "Address Input", G4 A13 (in) "Address Input", G5 ~{WE} (in) "Write Enable Input", G6 I/O7 (io) "Data Input/Output", H1 NC "No Connection", H2 A8 (in) "Address Input", H3 A9 (in) "Address Input", H4 A10 (in) "Address Input", H5 A11 (in) "Address Input", H6 NC "No Connection"

## IS61WV12816EDBLL-10BI-TR
designator U?
2 M High Speed Asynchronous CMOS SRAM with ECC, 128 K x 16, -40 to 85 degC, 48-Pin BGA (TF-BGA-48); Manufacturer: Integrated Silicon Solution Inc (ISSI); PartNumber: IS61WV12816EDBLL-10BI-TR; Density: 2M; Packing: Tape & Reel; Speed (ns): 10
footprint ISSI-TF-BGA-48-6000X8000DE (BGA, 48-Balls, Body 8x6mm, Pitch 0.75mm)
pins: A1 ~{LB} (in) "Lower-byte Control (I/O0-I/O7)", A2 ~{OE} (in) "Output Enable Input", A3 A0 (in) "Address Input", A4 A1 (in) "Address Input", A5 A2 (in) "Address Input", A6 NC "No Connection", B1 I/O8 (io) "Data Input/Output", B2 ~{UB} (in) "Upper-byte Control (I/O8-I/O15)", B3 A3 (in) "Address Input", B4 A4 (in) "Address Input", B5 ~{CE} (in) "Chip Enable Input", B6 I/O0 (io) "Data Input/Output", C1 I/O9 (io) "Data Input/Output", C2 I/O10 (io) "Data Input/Output", C3 A5 (in) "Address Input", C4 A6 (in) "Address Input", C5 I/O1 (io) "Data Input/Output", C6 I/O2 (io) "Data Input/Output", D1 GND (power) "Ground", D2 I/O11 (io) "Data Input/Output", D3 A17 (in) "Address Input", D4 A7 (in) "Address Input", D5 I/O3 (io) "Data Input/Output", D6 VDD (power) "Power", E1 VDD (power) "Power", E2 I/O12 (io) "Data Input/Output", E3 NC "No Connection", E4 A16 (in) "Address Input", E5 I/O4 (io) "Data Input/Output", E6 GND (power) "Ground", F1 I/O14 (io) "Data Input/Output", F2 I/O13 (io) "Data Input/Output", F3 A14 (in) "Address Input", F4 A15 (in) "Address Input", F5 I/O5 (io) "Data Input/Output", F6 I/O6 (io) "Data Input/Output", G1 I/O15 (io) "Data Input/Output", G2 NC "No Connection", G3 A12 (in) "Address Input", G4 A13 (in) "Address Input", G5 ~{WE} (in) "Write Enable Input", G6 I/O7 (io) "Data Input/Output", H1 NC "No Connection", H2 A8 (in) "Address Input", H3 A9 (in) "Address Input", H4 A10 (in) "Address Input", H5 A11 (in) "Address Input", H6 NC "No Connection"

## IS61WV12816EDBLL-10BLI
designator U?
2 M High Speed Asynchronous CMOS SRAM with ECC, 128 K x 16, -40 to 85 degC, 48-Pin BGA (TF-BGA-48), Pb-Free; Manufacturer: Integrated Silicon Solution Inc (ISSI); PartNumber: IS61WV12816EDBLL-10BLI; Density: 2M; Packing: Tray / Tube; Speed (ns): 10
footprint ISSI-TF-BGA-48-6000X8000DE (BGA, 48-Balls, Body 8x6mm, Pitch 0.75mm)
pins: A1 ~{LB} (in) "Lower-byte Control (I/O0-I/O7)", A2 ~{OE} (in) "Output Enable Input", A3 A0 (in) "Address Input", A4 A1 (in) "Address Input", A5 A2 (in) "Address Input", A6 NC "No Connection", B1 I/O8 (io) "Data Input/Output", B2 ~{UB} (in) "Upper-byte Control (I/O8-I/O15)", B3 A3 (in) "Address Input", B4 A4 (in) "Address Input", B5 ~{CE} (in) "Chip Enable Input", B6 I/O0 (io) "Data Input/Output", C1 I/O9 (io) "Data Input/Output", C2 I/O10 (io) "Data Input/Output", C3 A5 (in) "Address Input", C4 A6 (in) "Address Input", C5 I/O1 (io) "Data Input/Output", C6 I/O2 (io) "Data Input/Output", D1 GND (power) "Ground", D2 I/O11 (io) "Data Input/Output", D3 A17 (in) "Address Input", D4 A7 (in) "Address Input", D5 I/O3 (io) "Data Input/Output", D6 VDD (power) "Power", E1 VDD (power) "Power", E2 I/O12 (io) "Data Input/Output", E3 NC "No Connection", E4 A16 (in) "Address Input", E5 I/O4 (io) "Data Input/Output", E6 GND (power) "Ground", F1 I/O14 (io) "Data Input/Output", F2 I/O13 (io) "Data Input/Output", F3 A14 (in) "Address Input", F4 A15 (in) "Address Input", F5 I/O5 (io) "Data Input/Output", F6 I/O6 (io) "Data Input/Output", G1 I/O15 (io) "Data Input/Output", G2 NC "No Connection", G3 A12 (in) "Address Input", G4 A13 (in) "Address Input", G5 ~{WE} (in) "Write Enable Input", G6 I/O7 (io) "Data Input/Output", H1 NC "No Connection", H2 A8 (in) "Address Input", H3 A9 (in) "Address Input", H4 A10 (in) "Address Input", H5 A11 (in) "Address Input", H6 NC "No Connection"

## IS61WV12816EDBLL-10BLI-TR
designator U?
2 M High Speed Asynchronous CMOS SRAM with ECC, 128 K x 16, -40 to 85 degC, 48-Pin BGA (TF-BGA-48), Pb-Free; Manufacturer: Integrated Silicon Solution Inc (ISSI); PartNumber: IS61WV12816EDBLL-10BLI-TR; Density: 2M; Packing: Tape & Reel; Speed (ns): 10
footprint ISSI-TF-BGA-48-6000X8000DE (BGA, 48-Balls, Body 8x6mm, Pitch 0.75mm)
pins: A1 ~{LB} (in) "Lower-byte Control (I/O0-I/O7)", A2 ~{OE} (in) "Output Enable Input", A3 A0 (in) "Address Input", A4 A1 (in) "Address Input", A5 A2 (in) "Address Input", A6 NC "No Connection", B1 I/O8 (io) "Data Input/Output", B2 ~{UB} (in) "Upper-byte Control (I/O8-I/O15)", B3 A3 (in) "Address Input", B4 A4 (in) "Address Input", B5 ~{CE} (in) "Chip Enable Input", B6 I/O0 (io) "Data Input/Output", C1 I/O9 (io) "Data Input/Output", C2 I/O10 (io) "Data Input/Output", C3 A5 (in) "Address Input", C4 A6 (in) "Address Input", C5 I/O1 (io) "Data Input/Output", C6 I/O2 (io) "Data Input/Output", D1 GND (power) "Ground", D2 I/O11 (io) "Data Input/Output", D3 A17 (in) "Address Input", D4 A7 (in) "Address Input", D5 I/O3 (io) "Data Input/Output", D6 VDD (power) "Power", E1 VDD (power) "Power", E2 I/O12 (io) "Data Input/Output", E3 NC "No Connection", E4 A16 (in) "Address Input", E5 I/O4 (io) "Data Input/Output", E6 GND (power) "Ground", F1 I/O14 (io) "Data Input/Output", F2 I/O13 (io) "Data Input/Output", F3 A14 (in) "Address Input", F4 A15 (in) "Address Input", F5 I/O5 (io) "Data Input/Output", F6 I/O6 (io) "Data Input/Output", G1 I/O15 (io) "Data Input/Output", G2 NC "No Connection", G3 A12 (in) "Address Input", G4 A13 (in) "Address Input", G5 ~{WE} (in) "Write Enable Input", G6 I/O7 (io) "Data Input/Output", H1 NC "No Connection", H2 A8 (in) "Address Input", H3 A9 (in) "Address Input", H4 A10 (in) "Address Input", H5 A11 (in) "Address Input", H6 NC "No Connection"

## IS61WV12816EDBLL-10TI
designator U?
2 M High Speed Asynchronous CMOS SRAM with ECC, 128 K x 16, -40 to 85 degC, 44-Pin SOP (TSOP-2-44); Manufacturer: Integrated Silicon Solution Inc (ISSI); PartNumber: IS61WV12816EDBLL-10TI; Density: 2M; Packing: Tray / Tube; Speed (ns): 10
footprint ISSI-TSOP-2-44_N (SOP, 44-Leads, Body 18.5x10.3mm, Pitch 0.8mm, IPC Medium Density)
pins: 1 A4 (in) "Address Input", 2 A3 (in) "Address Input", 3 A2 (in) "Address Input", 4 A1 (in) "Address Input", 5 A0 (in) "Address Input", 6 ~{CE} (in) "Chip Enable Input", 7 I/O0 (io) "Data Input/Output", 8 I/O1 (io) "Data Input/Output", 9 I/O2 (io) "Data Input/Output", 10 I/O3 (io) "Data Input/Output", 11 VDD (power) "Power", 12 GND (power) "Ground", 13 I/O4 (io) "Data Input/Output", 14 I/O5 (io) "Data Input/Output", 15 I/O6 (io) "Data Input/Output", 16 I/O7 (io) "Data Input/Output", 17 ~{WE} (in) "Write Enable Input", 18 A16 (in) "Address Input", 19 A15 (in) "Address Input", 20 A14 (in) "Address Input", 21 A13 (in) "Address Input", 22 A12 (in) "Address Input", 23 NC "No Connection", 24 A11 (in) "Address Input", 25 A10 (in) "Address Input", 26 A9 (in) "Address Input", 27 A8 (in) "Address Input", 28 NC "No Connection", 29 I/O8 (io) "Data Input/Output", 30 I/O9 (io) "Data Input/Output", 31 I/O10 (io) "Data Input/Output", 32 I/O11 (io) "Data Input/Output", 33 VDD (power) "Power", 34 GND (power) "Ground", 35 I/O12 (io) "Data Input/Output", 36 I/O13 (io) "Data Input/Output", 37 I/O14 (io) "Data Input/Output", 38 I/O15 (io) "Data Input/Output", 39 ~{LB} (in) "Lower-byte Control (I/O0-I/O7)", 40 ~{UB} (in) "Upper-byte Control (I/O8-I/O15)", 41 ~{OE} (in) "Output Enable Input", 42 A7 (in) "Address Input", 43 A6 (in) "Address Input", 44 A5 (in) "Address Input"

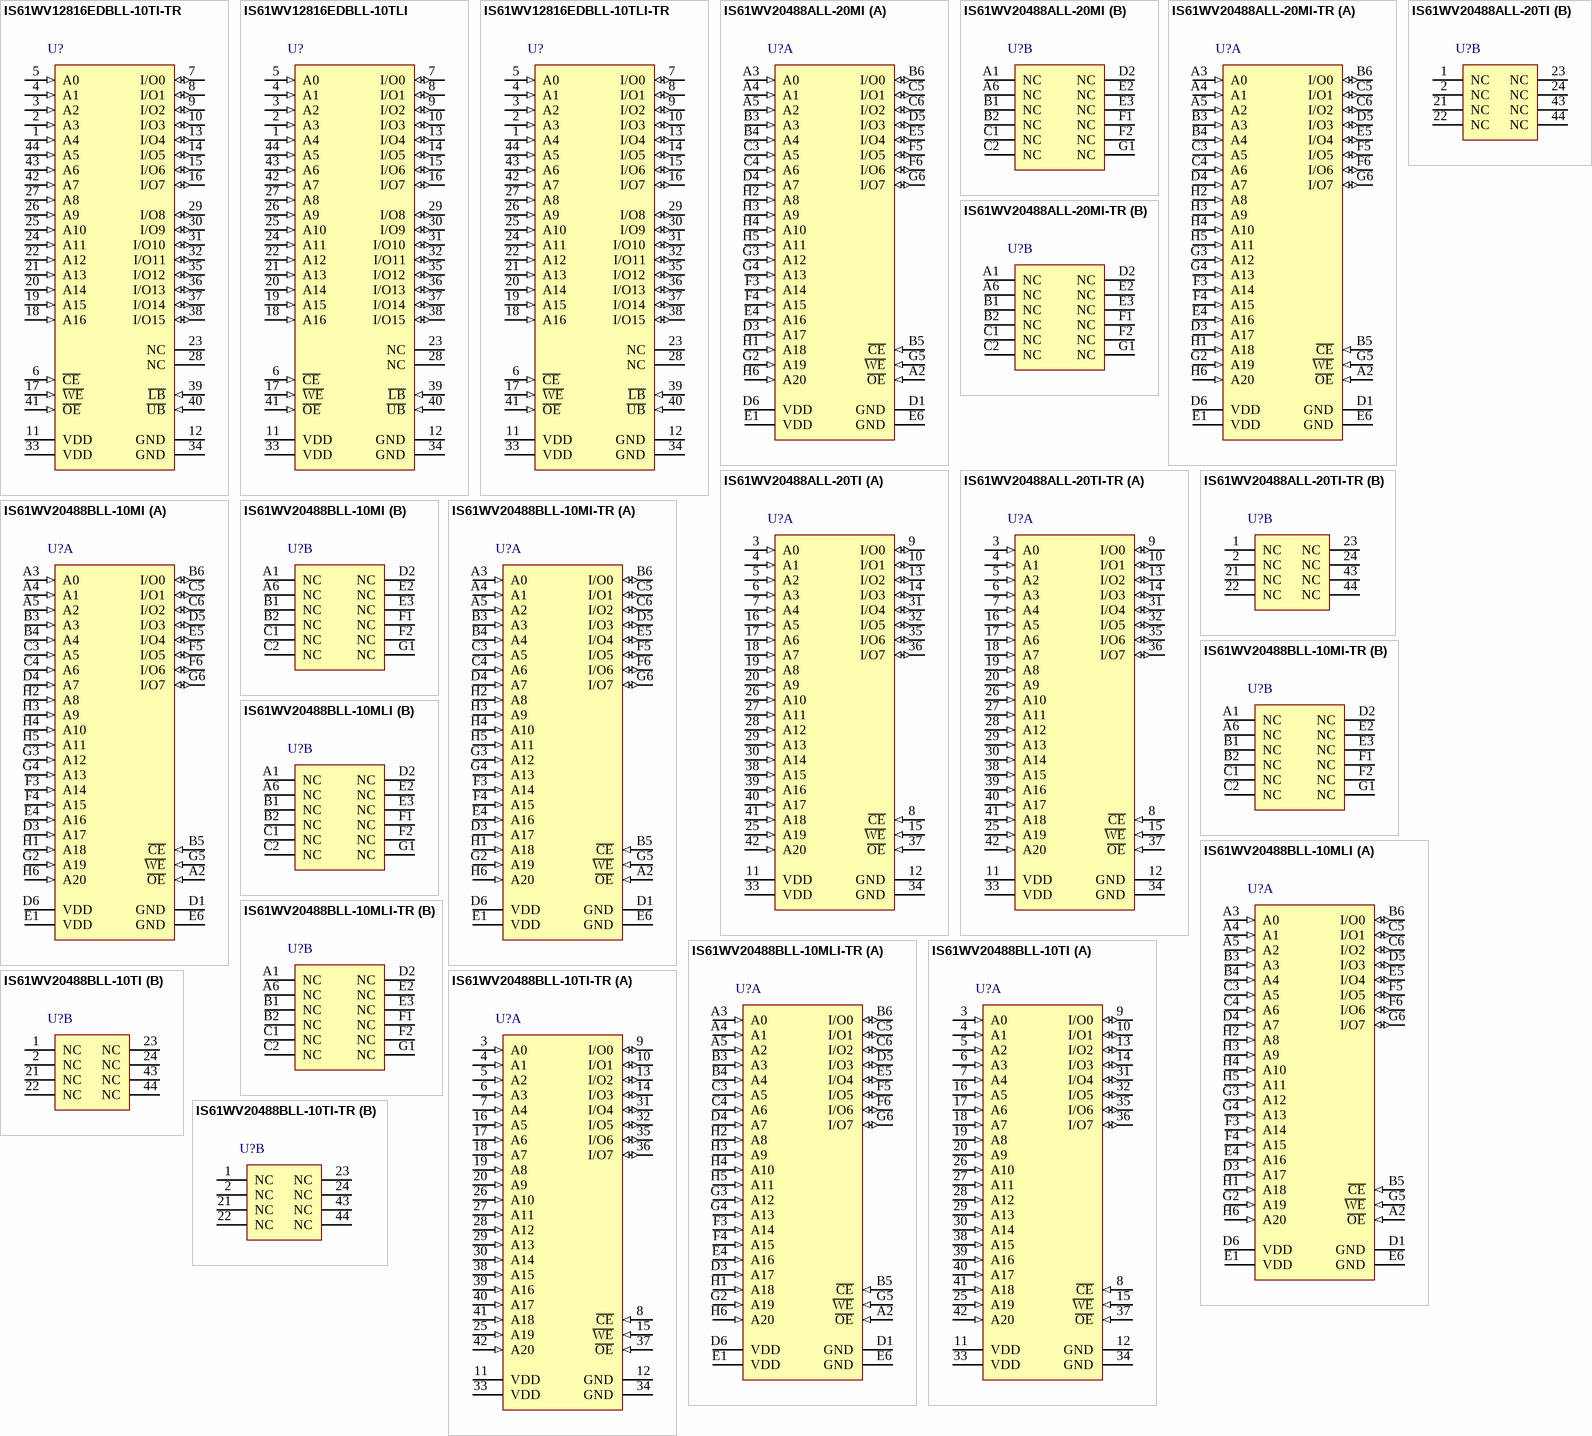
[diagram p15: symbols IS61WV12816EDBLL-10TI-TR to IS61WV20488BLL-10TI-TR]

## IS61WV12816EDBLL-10TI-TR
designator U?
2 M High Speed Asynchronous CMOS SRAM with ECC, 128 K x 16, -40 to 85 degC, 44-Pin SOP (TSOP-2-44); Manufacturer: Integrated Silicon Solution Inc (ISSI); PartNumber: IS61WV12816EDBLL-10TI-TR; Density: 2M; Packing: Tape & Reel; Speed (ns): 10
footprint ISSI-TSOP-2-44_N (SOP, 44-Leads, Body 18.5x10.3mm, Pitch 0.8mm, IPC Medium Density)
pins: 1 A4 (in) "Address Input", 2 A3 (in) "Address Input", 3 A2 (in) "Address Input", 4 A1 (in) "Address Input", 5 A0 (in) "Address Input", 6 ~{CE} (in) "Chip Enable Input", 7 I/O0 (io) "Data Input/Output", 8 I/O1 (io) "Data Input/Output", 9 I/O2 (io) "Data Input/Output", 10 I/O3 (io) "Data Input/Output", 11 VDD (power) "Power", 12 GND (power) "Ground", 13 I/O4 (io) "Data Input/Output", 14 I/O5 (io) "Data Input/Output", 15 I/O6 (io) "Data Input/Output", 16 I/O7 (io) "Data Input/Output", 17 ~{WE} (in) "Write Enable Input", 18 A16 (in) "Address Input", 19 A15 (in) "Address Input", 20 A14 (in) "Address Input", 21 A13 (in) "Address Input", 22 A12 (in) "Address Input", 23 NC "No Connection", 24 A11 (in) "Address Input", 25 A10 (in) "Address Input", 26 A9 (in) "Address Input", 27 A8 (in) "Address Input", 28 NC "No Connection", 29 I/O8 (io) "Data Input/Output", 30 I/O9 (io) "Data Input/Output", 31 I/O10 (io) "Data Input/Output", 32 I/O11 (io) "Data Input/Output", 33 VDD (power) "Power", 34 GND (power) "Ground", 35 I/O12 (io) "Data Input/Output", 36 I/O13 (io) "Data Input/Output", 37 I/O14 (io) "Data Input/Output", 38 I/O15 (io) "Data Input/Output", 39 ~{LB} (in) "Lower-byte Control (I/O0-I/O7)", 40 ~{UB} (in) "Upper-byte Control (I/O8-I/O15)", 41 ~{OE} (in) "Output Enable Input", 42 A7 (in) "Address Input", 43 A6 (in) "Address Input", 44 A5 (in) "Address Input"

## IS61WV12816EDBLL-10TLI
designator U?
2 M High Speed Asynchronous CMOS SRAM with ECC, 128 K x 16, -40 to 85 degC, 44-Pin SOP (TSOP-2-44), Pb-Free; Manufacturer: Integrated Silicon Solution Inc (ISSI); PartNumber: IS61WV12816EDBLL-10TLI; Density: 2M; Packing: Tray / Tube; Speed (ns): 10
footprint ISSI-TSOP-2-44_N (SOP, 44-Leads, Body 18.5x10.3mm, Pitch 0.8mm, IPC Medium Density)
pins: 1 A4 (in) "Address Input", 2 A3 (in) "Address Input", 3 A2 (in) "Address Input", 4 A1 (in) "Address Input", 5 A0 (in) "Address Input", 6 ~{CE} (in) "Chip Enable Input", 7 I/O0 (io) "Data Input/Output", 8 I/O1 (io) "Data Input/Output", 9 I/O2 (io) "Data Input/Output", 10 I/O3 (io) "Data Input/Output", 11 VDD (power) "Power", 12 GND (power) "Ground", 13 I/O4 (io) "Data Input/Output", 14 I/O5 (io) "Data Input/Output", 15 I/O6 (io) "Data Input/Output", 16 I/O7 (io) "Data Input/Output", 17 ~{WE} (in) "Write Enable Input", 18 A16 (in) "Address Input", 19 A15 (in) "Address Input", 20 A14 (in) "Address Input", 21 A13 (in) "Address Input", 22 A12 (in) "Address Input", 23 NC "No Connection", 24 A11 (in) "Address Input", 25 A10 (in) "Address Input", 26 A9 (in) "Address Input", 27 A8 (in) "Address Input", 28 NC "No Connection", 29 I/O8 (io) "Data Input/Output", 30 I/O9 (io) "Data Input/Output", 31 I/O10 (io) "Data Input/Output", 32 I/O11 (io) "Data Input/Output", 33 VDD (power) "Power", 34 GND (power) "Ground", 35 I/O12 (io) "Data Input/Output", 36 I/O13 (io) "Data Input/Output", 37 I/O14 (io) "Data Input/Output", 38 I/O15 (io) "Data Input/Output", 39 ~{LB} (in) "Lower-byte Control (I/O0-I/O7)", 40 ~{UB} (in) "Upper-byte Control (I/O8-I/O15)", 41 ~{OE} (in) "Output Enable Input", 42 A7 (in) "Address Input", 43 A6 (in) "Address Input", 44 A5 (in) "Address Input"

## IS61WV12816EDBLL-10TLI-TR
designator U?
2 M High Speed Asynchronous CMOS SRAM with ECC, 128 K x 16, -40 to 85 degC, 44-Pin SOP (TSOP-2-44), Pb-Free; Manufacturer: Integrated Silicon Solution Inc (ISSI); PartNumber: IS61WV12816EDBLL-10TLI-TR; Density: 2M; Packing: Tape & Reel; Speed (ns): 10
footprint ISSI-TSOP-2-44_N (SOP, 44-Leads, Body 18.5x10.3mm, Pitch 0.8mm, IPC Medium Density)
pins: 1 A4 (in) "Address Input", 2 A3 (in) "Address Input", 3 A2 (in) "Address Input", 4 A1 (in) "Address Input", 5 A0 (in) "Address Input", 6 ~{CE} (in) "Chip Enable Input", 7 I/O0 (io) "Data Input/Output", 8 I/O1 (io) "Data Input/Output", 9 I/O2 (io) "Data Input/Output", 10 I/O3 (io) "Data Input/Output", 11 VDD (power) "Power", 12 GND (power) "Ground", 13 I/O4 (io) "Data Input/Output", 14 I/O5 (io) "Data Input/Output", 15 I/O6 (io) "Data Input/Output", 16 I/O7 (io) "Data Input/Output", 17 ~{WE} (in) "Write Enable Input", 18 A16 (in) "Address Input", 19 A15 (in) "Address Input", 20 A14 (in) "Address Input", 21 A13 (in) "Address Input", 22 A12 (in) "Address Input", 23 NC "No Connection", 24 A11 (in) "Address Input", 25 A10 (in) "Address Input", 26 A9 (in) "Address Input", 27 A8 (in) "Address Input", 28 NC "No Connection", 29 I/O8 (io) "Data Input/Output", 30 I/O9 (io) "Data Input/Output", 31 I/O10 (io) "Data Input/Output", 32 I/O11 (io) "Data Input/Output", 33 VDD (power) "Power", 34 GND (power) "Ground", 35 I/O12 (io) "Data Input/Output", 36 I/O13 (io) "Data Input/Output", 37 I/O14 (io) "Data Input/Output", 38 I/O15 (io) "Data Input/Output", 39 ~{LB} (in) "Lower-byte Control (I/O0-I/O7)", 40 ~{UB} (in) "Upper-byte Control (I/O8-I/O15)", 41 ~{OE} (in) "Output Enable Input", 42 A7 (in) "Address Input", 43 A6 (in) "Address Input", 44 A5 (in) "Address Input"

## IS61WV20488ALL-20MI
designator U?
16 M High Speed CMOS SRAM, 2 M x 8, -40 to 85 degC, 48-Pin BGA (TF-BGA-48); Manufacturer: Integrated Silicon Solution Inc (ISSI); PartNumber: IS61WV20488ALL-20MI; Organization: 2M x 8; Packing: Tray / Tube; Speed (ns): 20
footprint ISSI-TF-BGA-48-9000x11000DE (BGA, 48-Balls, Body 11x9mm, Pitch 0.75mm)
part A pins: A2 ~{OE} (in) "Output Enable Input", A3 A0 (in) "Address Input", A4 A1 (in) "Address Input", A5 A2 (in) "Address Input", B3 A3 (in) "Address Input", B4 A4 (in) "Address Input", B5 ~{CE} (in) "Chip Enable Input", B6 I/O0 (io) "Data Input / Output", C3 A5 (in) "Address Input", C4 A6 (in) "Address Input", C5 I/O1 (io) "Data Input / Output", C6 I/O2 (io) "Data Input / Output", D1 GND (power) "Ground", D3 A17 (in) "Address Input", D4 A7 (in) "Address Input", D5 I/O3 (io) "Data Input / Output", D6 VDD (power) "Power", E1 VDD (power) "Power", E4 A16 (in) "Address Input", E5 I/O4 (io) "Data Input / Output", E6 GND (power) "Ground", F3 A14 (in) "Address Input", F4 A15 (in) "Address Input", F5 I/O5 (io) "Data Input / Output", F6 I/O6 (io) "Data Input / Output", G2 A19 (in) "Address Input", G3 A12 (in) "Address Input", G4 A13 (in) "Address Input", G5 ~{WE} (in) "Write Enable Input", G6 I/O7 (io) "Data Input / Output", H1 A18 (in) "Address Input", H2 A8 (in) "Address Input", H3 A9 (in) "Address Input", H4 A10 (in) "Address Input", H5 A11 (in) "Address Input", H6 A20 (in) "Address Input"
part B pins: A1 NC "No Connection", A6 NC "No Connection", B1 NC "No Connection", B2 NC "No Connection", C1 NC "No Connection", C2 NC "No Connection", D2 NC "No Connection", E2 NC "No Connection", E3 NC "No Connection", F1 NC "No Connection", F2 NC "No Connection", G1 NC "No Connection"

## IS61WV20488ALL-20MI-TR
designator U?
16 M High Speed CMOS SRAM, 2 M x 8, -40 to 85 degC, 48-Pin BGA (TF-BGA-48); Manufacturer: Integrated Silicon Solution Inc (ISSI); PartNumber: IS61WV20488ALL-20MI-TR; Organization: 2M x 8; Packing: Tape & Reel; Speed (ns): 20
footprint ISSI-TF-BGA-48-9000x11000DE (BGA, 48-Balls, Body 11x9mm, Pitch 0.75mm)
part A pins: A2 ~{OE} (in) "Output Enable Input", A3 A0 (in) "Address Input", A4 A1 (in) "Address Input", A5 A2 (in) "Address Input", B3 A3 (in) "Address Input", B4 A4 (in) "Address Input", B5 ~{CE} (in) "Chip Enable Input", B6 I/O0 (io) "Data Input / Output", C3 A5 (in) "Address Input", C4 A6 (in) "Address Input", C5 I/O1 (io) "Data Input / Output", C6 I/O2 (io) "Data Input / Output", D1 GND (power) "Ground", D3 A17 (in) "Address Input", D4 A7 (in) "Address Input", D5 I/O3 (io) "Data Input / Output", D6 VDD (power) "Power", E1 VDD (power) "Power", E4 A16 (in) "Address Input", E5 I/O4 (io) "Data Input / Output", E6 GND (power) "Ground", F3 A14 (in) "Address Input", F4 A15 (in) "Address Input", F5 I/O5 (io) "Data Input / Output", F6 I/O6 (io) "Data Input / Output", G2 A19 (in) "Address Input", G3 A12 (in) "Address Input", G4 A13 (in) "Address Input", G5 ~{WE} (in) "Write Enable Input", G6 I/O7 (io) "Data Input / Output", H1 A18 (in) "Address Input", H2 A8 (in) "Address Input", H3 A9 (in) "Address Input", H4 A10 (in) "Address Input", H5 A11 (in) "Address Input", H6 A20 (in) "Address Input"
part B pins: A1 NC "No Connection", A6 NC "No Connection", B1 NC "No Connection", B2 NC "No Connection", C1 NC "No Connection", C2 NC "No Connection", D2 NC "No Connection", E2 NC "No Connection", E3 NC "No Connection", F1 NC "No Connection", F2 NC "No Connection", G1 NC "No Connection"

## IS61WV20488ALL-20TI
designator U?
16 M High Speed CMOS SRAM, 2 M x 8, -40 to 85 degC, 44-Pin SOP (TSOP-2-44); Manufacturer: Integrated Silicon Solution Inc (ISSI); PartNumber: IS61WV20488ALL-20TI; Organization: 2M x 8; Packing: Tray / Tube; Speed (ns): 20
footprint ISSI-TSOP-2-44_N (SOP, 44-Leads, Body 18.5x10.3mm, Pitch 0.8mm, IPC Medium Density)
part A pins: 3 A0 (in) "Address Inputs", 4 A1 (in) "Address Inputs", 5 A2 (in) "Address Inputs", 6 A3 (in) "Address Inputs", 7 A4 (in) "Address Inputs", 8 ~{CE} (in) "Chip Enable Input", 9 I/O0 (io) "Data Input / Output", 10 I/O1 (io) "Data Input / Output", 11 VDD (power) "Power", 12 GND (power) "Ground", 13 I/O2 (io) "Data Input / Output", 14 I/O3 (io) "Data Input / Output", 15 ~{WE} (in) "Write Enable Input", 16 A5 (in) "Address Inputs", 17 A6 (in) "Address Inputs", 18 A7 (in) "Address Inputs", 19 A8 (in) "Address Inputs", 20 A9 (in) "Address Inputs", 25 A19 (in) "Address Inputs", 26 A10 (in) "Address Inputs", 27 A11 (in) "Address Inputs", 28 A12 (in) "Address Inputs", 29 A13 (in) "Address Inputs", 30 A14 (in) "Address Inputs", 31 I/O4 (io) "Data Input / Output", 32 I/O5 (io) "Data Input / Output", 33 VDD (power) "Power", 34 GND (power) "Ground", 35 I/O6 (io) "Data Input / Output", 36 I/O7 (io) "Data Input / Output", 37 ~{OE} (in) "Output Enable Input", 38 A15 (in) "Address Inputs", 39 A16 (in) "Address Inputs", 40 A17 (in) "Address Inputs", 41 A18 (in) "Address Inputs", 42 A20 (in) "Address Inputs"
part B pins: 1 NC "No Connection", 2 NC "No Connection", 21 NC "No Connection", 22 NC "No Connection", 23 NC "No Connection", 24 NC "No Connection", 43 NC "No Connection", 44 NC "No Connection"

## IS61WV20488ALL-20TI-TR
designator U?
16 M High Speed CMOS SRAM, 2 M x 8, -40 to 85 degC, 44-Pin SOP (TSOP-2-44); Manufacturer: Integrated Silicon Solution Inc (ISSI); PartNumber: IS61WV20488ALL-20TI-TR; Organization: 2M x 8; Packing: Tape & Reel; Speed (ns): 20
footprint ISSI-TSOP-2-44_N (SOP, 44-Leads, Body 18.5x10.3mm, Pitch 0.8mm, IPC Medium Density)
part A pins: 3 A0 (in) "Address Inputs", 4 A1 (in) "Address Inputs", 5 A2 (in) "Address Inputs", 6 A3 (in) "Address Inputs", 7 A4 (in) "Address Inputs", 8 ~{CE} (in) "Chip Enable Input", 9 I/O0 (io) "Data Input / Output", 10 I/O1 (io) "Data Input / Output", 11 VDD (power) "Power", 12 GND (power) "Ground", 13 I/O2 (io) "Data Input / Output", 14 I/O3 (io) "Data Input / Output", 15 ~{WE} (in) "Write Enable Input", 16 A5 (in) "Address Inputs", 17 A6 (in) "Address Inputs", 18 A7 (in) "Address Inputs", 19 A8 (in) "Address Inputs", 20 A9 (in) "Address Inputs", 25 A19 (in) "Address Inputs", 26 A10 (in) "Address Inputs", 27 A11 (in) "Address Inputs", 28 A12 (in) "Address Inputs", 29 A13 (in) "Address Inputs", 30 A14 (in) "Address Inputs", 31 I/O4 (io) "Data Input / Output", 32 I/O5 (io) "Data Input / Output", 33 VDD (power) "Power", 34 GND (power) "Ground", 35 I/O6 (io) "Data Input / Output", 36 I/O7 (io) "Data Input / Output", 37 ~{OE} (in) "Output Enable Input", 38 A15 (in) "Address Inputs", 39 A16 (in) "Address Inputs", 40 A17 (in) "Address Inputs", 41 A18 (in) "Address Inputs", 42 A20 (in) "Address Inputs"
part B pins: 1 NC "No Connection", 2 NC "No Connection", 21 NC "No Connection", 22 NC "No Connection", 23 NC "No Connection", 24 NC "No Connection", 43 NC "No Connection", 44 NC "No Connection"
